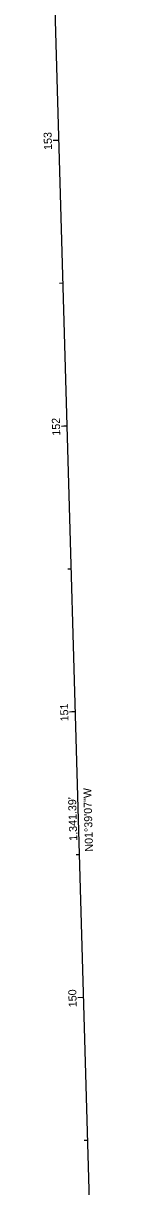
# Model space of a CAD drawing. Extents: x 177110 to 177558, y 286252 to 294117.
# Drawn here: x 177261.2 to 177303.4, y 290669.2 to 291076.2 of the extents above; entities that cross this region are included whole.
import ezdxf

# ---------------------------------------------------------------- set-up
doc = ezdxf.new("R2010")
doc.units = 0
for name, color, linetype in [('GE_X_Alignment_500_Bearings', 7, 'Continuous'), ('GE_X_Alignment_500_Distances', 7, 'Continuous'), ('GE_X_Alignment_500_Stations', 7, 'Continuous'), ('RW_X_CL', 7, 'Continuous'), ('RW_X_CL_100_Bearings', 7, 'Continuous'), ('RW_X_CL_100_Distances', 7, 'Continuous'), ('RW_X_CL_100_Stations', 7, 'Continuous'), ('SC_Scratch1', 7, 'Continuous')]:
    doc.layers.add(name, color=color, linetype=linetype)

msp = doc.modelspace()

# ---------------------------------------------------------------- linework, layer by layer
at = {"layer": 'GE_X_Alignment_500_Stations'}
for p, q in [((177273.72, 291035.25), (177272.52, 291035.22)), ((177276.6, 290935.29), (177275.4, 290935.26)), ((177279.48, 290835.33), (177278.28, 290835.3)), ((177282.36, 290735.38), (177280.36, 290735.32))]:
    msp.add_line(p, q, dxfattribs=at)
at = {"layer": 'RW_X_CL'}
msp.add_line((177299.88, 290127.96), (177261.21, 291468.79), dxfattribs=at)
at = {"layer": 'RW_X_CL_100_Stations'}
for p, q in [((177273.72, 291035.25), (177271.72, 291035.19)), ((177275.16, 290985.27), (177273.96, 290985.24)), ((177276.6, 290935.29), (177274.6, 290935.23)), ((177278.04, 290885.31), (177276.84, 290885.28)), ((177279.48, 290835.33), (177277.48, 290835.28)), ((177280.92, 290785.35), (177279.72, 290785.32)), ((177282.36, 290735.38), (177280.36, 290735.32)), ((177283.81, 290685.4), (177282.61, 290685.36))]:
    msp.add_line(p, q, dxfattribs=at)
at = {"layer": 'SC_Scratch1'}
msp.add_line((177303.45, 290004.39), (177261.21, 291468.79), dxfattribs=at)

# ---------------------------------------------------------------- texts
at = {"layer": 'GE_X_Alignment_500_Bearings'}
msp.add_text('N01°39\'07"W', height=2.8, rotation=91.6519, dxfattribs=at).set_placement((177285.69, 290786.48))
at = {"layer": 'GE_X_Alignment_500_Distances'}
msp.add_text("1,341.39'", height=2.8, rotation=91.6519, dxfattribs=at).set_placement((177280.16, 290790.26))
at = {"layer": 'GE_X_Alignment_500_Stations'}
msp.add_text('150', height=2.8, rotation=91.6519, dxfattribs=at).set_placement((177279.96, 290732.04))
at = {"layer": 'RW_X_CL_100_Bearings'}
msp.add_text('N01°39\'07"W', height=2.8, rotation=91.6519, dxfattribs=at).set_placement((177285.69, 290786.48))
at = {"layer": 'RW_X_CL_100_Distances'}
msp.add_text("1,341.39'", height=2.8, rotation=91.6519, dxfattribs=at).set_placement((177280.16, 290790.26))
at = {"layer": 'RW_X_CL_100_Stations'}
for s, p in [('153', (177271.31, 291031.98)), ('152', (177274.19, 290932.01)), ('151', (177277.08, 290832.04)), ('150', (177279.96, 290732.04))]:
    msp.add_text(s, height=2.8, rotation=91.6519, dxfattribs=at).set_placement(p)

doc.saveas('drawing.dxf')
